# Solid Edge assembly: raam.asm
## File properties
Author: Mac
Template: Normal.asm
Last saved by: Mac
Revision: 11
Application: Solid Edge
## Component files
lyhike_karp.psm
pikk_karp.psm
polt.asm
vahetykk.psm
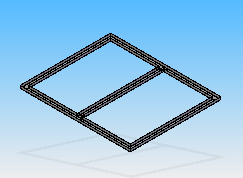
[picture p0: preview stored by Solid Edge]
